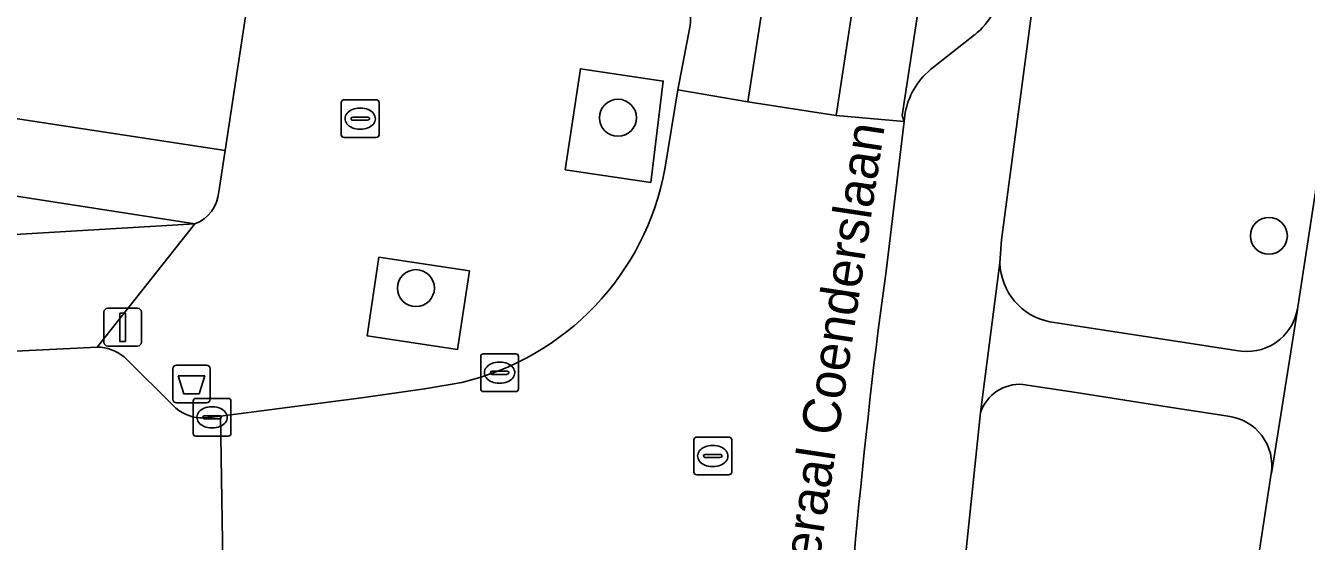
# Model space of a CAD drawing. Extents: x 161084 to 161928, y 385354 to 386522.
# Drawn here: x 161622.73 to 161656.61, y 385454.78 to 385468.42 of the extents above; entities that cross this region are included whole.
import ezdxf

# ---------------------------------------------------------------- set-up
doc = ezdxf.new("R2010")
doc.units = 0
for name, color, linetype in [('IMGEO_Afvalbak', 7, 'Continuous'), ('IMGEO_Boom', 7, 'Continuous'), ('IMGEO_Brandkraan', 7, 'Continuous'), ('IMGEO_Fietspad_gesloten', 7, 'Continuous'), ('IMGEO_Groenvoorziening', 7, 'Continuous'), ('IMGEO_Kolk', 7, 'Continuous'), ('IMGEO_Lichtmast', 7, 'Continuous'), ('IMGEO_Openbare_ruimte_label', 7, 'Continuous'), ('IMGEO_Pand', 7, 'Continuous'), ('IMGEO_Parkeervlak_open', 7, 'Continuous'), ('IMGEO_Rijbaan_lokaal_gesloten', 7, 'Continuous'), ('IMGEO_Rijbaan_lokaal_open', 7, 'Continuous'), ('IMGEO_Rioolput', 7, 'Continuous'), ('IMGEO_Voetpad_open', 7, 'Continuous')]:
    doc.layers.add(name, color=color, linetype=linetype)

msp = doc.modelspace()

# ---------------------------------------------------------------- linework, layer by layer
at = {"layer": 'IMGEO_Afvalbak'}
for p, q in [((161626.622, 385458.538), (161626.622, 385459.338)), ((161626.622, 385459.338), (161626.622, 385458.538)), ((161626.722, 385459.438), (161627.512, 385459.438)), ((161627.512, 385459.438), (161626.722, 385459.438)), ((161627.612, 385459.338), (161627.612, 385458.538)), ((161627.612, 385458.538), (161627.612, 385459.338)), ((161627.512, 385458.438), (161626.722, 385458.438)), ((161626.722, 385458.438), (161627.512, 385458.438))]:
    msp.add_line(p, q, dxfattribs=at)
msp.add_lwpolyline([(161626.765, 385459.152), (161627.469, 385459.152), (161627.32, 385458.682), (161626.914, 385458.682), (161626.765, 385459.152)], dxfattribs=at)
for centre, start, end in [((161626.722, 385459.338), 90, 180), ((161626.722, 385459.338), 90, 180), ((161627.512, 385459.338), 0, 90), ((161627.512, 385459.338), 360, 90), ((161626.722, 385458.538), 180, 270), ((161626.722, 385458.538), 180, 270), ((161627.512, 385458.538), 270, 0), ((161627.512, 385458.538), 270, 0)]:
    msp.add_arc(centre, 0.1, start, end, dxfattribs=at)
at = {"layer": 'IMGEO_Boom'}
for centre in [(161638.401, 385465.983), (161655.623, 385462.859), (161633.056, 385461.476)]:
    msp.add_circle(centre, 0.489, dxfattribs=at)
at = {"layer": 'IMGEO_Brandkraan'}
for p, q in [((161631.08, 385465.533), (161631.08, 385466.385)), ((161631.155, 385466.459), (161632.007, 385466.459)), ((161632.081, 385466.385), (161632.081, 385465.533)), ((161631.339, 385465.953), (161631.339, 385465.965)), ((161631.777, 385465.916), (161631.379, 385465.916)), ((161631.382, 385466.002), (161631.78, 385466.002)), ((161631.568, 385466.239), (161631.593, 385466.239)), ((161631.823, 385465.965), (161631.823, 385465.953)), ((161631.591, 385465.679), (161631.566, 385465.679)), ((161632.007, 385465.459), (161631.155, 385465.459))]:
    msp.add_line(p, q, dxfattribs=at)
for points in [[(161631.08, 385465.533), (161631.08, 385466.385)], [(161631.155, 385466.459), (161632.007, 385466.459)], [(161632.081, 385466.385), (161632.081, 385465.533)], [(161632.007, 385465.459), (161631.155, 385465.459)]]:
    msp.add_lwpolyline(points, dxfattribs=at)
for centre, radius, start, end in [((161631.157, 385466.383), 0.0765, 91.552, 178.448), ((161631.157, 385466.383), 0.0765, 91.552, 178.448), ((161632.005, 385466.383), 0.0765, 1.552, 88.448), ((161632.005, 385466.383), 0.0765, 1.552, 88.448), ((161631.379, 385465.962), 0.0403, 85.8775, 175.7526), ((161631.376, 385465.952), 0.0366, 178.938, 274.7102), ((161631.78, 385465.959), 0.043, 264.8664, 352.4533), ((161631.784, 385465.964), 0.0386, 1.7309, 96.639), ((161631.157, 385465.535), 0.0765, 181.552, 268.448), ((161631.157, 385465.535), 0.0765, 181.552, 268.448), ((161632.005, 385465.535), 0.0765, 271.552, 358.448), ((161632.005, 385465.535), 0.0765, 271.552, 358.448)]:
    msp.add_arc(centre, radius, start, end, dxfattribs=at)
for centre, major_axis, ratio, start_param, end_param in [((161631.567, 385465.959), (-0.387, 0.002), 0.722429, 4.712389, 7.853982), ((161631.592, 385465.959), (-0.39, 0.002), 0.717154, 1.570796, 4.712389)]:
    msp.add_ellipse(centre, major_axis=major_axis, ratio=ratio, start_param=start_param, end_param=end_param, dxfattribs=at)
at = {"layer": 'IMGEO_Fietspad_gesloten'}
for points in [[(161657.676, 385557.376), (161657.035, 385551.607), (161656.101, 385544.122), (161653.229, 385525.292), (161650.81, 385509.078), (161648.418, 385493.406), (161645.687, 385475.984), (161644.173, 385466.039), (161645.972, 385465.882), (161645.921, 385466.044), (161654.912, 385525.117), (161655.077, 385525.205), (161655.27, 385526.392)], [(161640.307, 385468.42), (161639.981, 385466.717), (161641.834, 385466.406), (161644.23, 385481.84), (161647.175, 385501.347), (161649.95, 385519.187)]]:
    msp.add_lwpolyline(points, dxfattribs=at)
msp.add_arc((161639.335, 385468.589), 0.987, 350.1456, 38.031, dxfattribs=at)
at = {"layer": 'IMGEO_Groenvoorziening'}
for points in [[(161656.38, 385460.922), (161658.19, 385472.711), (161661.817, 385496.26), (161663.625, 385508.283), (161667.803, 385536.052), (161668.116, 385538.133)], [(161661.208, 385537.956), (161659.14, 385524.383), (161657.879, 385524.571), (161655.178, 385507.25), (161651.761, 385484.769), (161649.596, 385470.673), (161648.548, 385462.752), (161648.507, 385462.144)], [(161649.829, 385460.581), (161650.74, 385460.441), (161653.046, 385460.089), (161654.755, 385459.827)], [(161654.544, 385458.088), (161652.934, 385458.337), (161650.52, 385458.711), (161649.115, 385458.928)], [(161647.993, 385458.185), (161647.537, 385453.796), (161647.198, 385449.946), (161647.015, 385446.776), (161646.866, 385440.852)], [(161653.085, 385439.584), (161655.028, 385452.288), (161655.683, 385456.575)]]:
    msp.add_lwpolyline(points, dxfattribs=at)
for points in [[(161637.008, 385464.609), (161639.269, 385464.266), (161639.601, 385466.954), (161637.407, 385467.281)], [(161634.472, 385461.937), (161632.074, 385462.292), (161631.765, 385460.216), (161634.155, 385459.85)]]:
    msp.add_lwpolyline(points, close=True, dxfattribs=at)
for centre, radius, start, end in [((161650.153, 385462.196), 1.647, 181.7969, 258.6528), ((161655.037, 385461.162), 1.364, 258.0731, 349.8747), ((161649.033, 385457.833), 1.098, 85.7166, 161.3093), ((161654.388, 385456.785), 1.312, 350.7925, 83.1531)]:
    msp.add_arc(centre, radius, start, end, dxfattribs=at)
at = {"layer": 'IMGEO_Kolk'}
for p, q in [((161634.769, 385458.812), (161634.769, 385459.664)), ((161634.844, 385459.738), (161635.696, 385459.738)), ((161635.257, 385459.518), (161635.282, 385459.518)), ((161635.77, 385459.664), (161635.77, 385458.812)), ((161635.028, 385459.232), (161635.028, 385459.244)), ((161635.466, 385459.195), (161635.068, 385459.195)), ((161635.071, 385459.281), (161635.469, 385459.281)), ((161635.512, 385459.244), (161635.512, 385459.232)), ((161635.28, 385458.958), (161635.255, 385458.958)), ((161627.16, 385457.632), (161627.16, 385458.484)), ((161627.235, 385458.558), (161628.087, 385458.558)), ((161628.161, 385458.484), (161628.161, 385457.632)), ((161635.696, 385458.738), (161634.844, 385458.738)), ((161627.648, 385458.338), (161627.673, 385458.338)), ((161627.419, 385458.052), (161627.419, 385458.064)), ((161627.857, 385458.015), (161627.459, 385458.015)), ((161627.462, 385458.101), (161627.86, 385458.101)), ((161627.671, 385457.778), (161627.646, 385457.778)), ((161627.903, 385458.064), (161627.903, 385458.052)), ((161628.087, 385457.558), (161627.235, 385457.558))]:
    msp.add_line(p, q, dxfattribs=at)
for points in [[(161634.769, 385458.812), (161634.769, 385459.664)], [(161634.844, 385459.738), (161635.696, 385459.738)], [(161635.77, 385459.664), (161635.77, 385458.812)], [(161627.16, 385457.632), (161627.16, 385458.484)], [(161627.235, 385458.558), (161628.087, 385458.558)], [(161628.161, 385458.484), (161628.161, 385457.632)], [(161635.696, 385458.738), (161634.844, 385458.738)], [(161628.087, 385457.558), (161627.235, 385457.558)]]:
    msp.add_lwpolyline(points, dxfattribs=at)
for centre, radius, start, end in [((161634.846, 385459.662), 0.0765, 91.552, 178.448), ((161634.846, 385459.662), 0.0765, 91.552, 178.448), ((161635.694, 385459.662), 0.0765, 1.552, 88.448), ((161635.694, 385459.662), 0.0765, 1.552, 88.448), ((161635.068, 385459.241), 0.0403, 85.8775, 175.7526), ((161635.065, 385459.231), 0.0366, 178.938, 274.7102), ((161635.469, 385459.238), 0.043, 264.8664, 352.4533), ((161635.473, 385459.243), 0.0386, 1.7309, 96.639), ((161634.846, 385458.814), 0.0765, 181.552, 268.448), ((161634.846, 385458.814), 0.0765, 181.552, 268.448), ((161635.694, 385458.814), 0.0765, 271.552, 358.448), ((161635.694, 385458.814), 0.0765, 271.552, 358.448), ((161627.237, 385458.482), 0.0765, 91.552, 178.448), ((161627.237, 385458.482), 0.0765, 91.552, 178.448), ((161628.085, 385458.482), 0.0765, 1.552, 88.448), ((161628.085, 385458.482), 0.0765, 1.552, 88.448), ((161627.459, 385458.061), 0.0403, 85.8775, 175.7526), ((161627.456, 385458.051), 0.0366, 178.938, 274.7102), ((161627.86, 385458.058), 0.043, 264.8664, 352.4533), ((161627.864, 385458.063), 0.0386, 1.7309, 96.639), ((161627.237, 385457.634), 0.0765, 181.552, 268.448), ((161627.237, 385457.634), 0.0765, 181.552, 268.448), ((161628.085, 385457.634), 0.0765, 271.552, 358.448), ((161628.085, 385457.634), 0.0765, 271.552, 358.448)]:
    msp.add_arc(centre, radius, start, end, dxfattribs=at)
for centre, major_axis, ratio, start_param, end_param in [((161635.256, 385459.238), (-0.387, 0.002), 0.722429, 4.712389, 7.853982), ((161635.281, 385459.238), (-0.39, 0.002), 0.717154, 1.570796, 4.712389), ((161627.647, 385458.058), (-0.387, 0.002), 0.722429, 4.712389, 7.853982), ((161627.672, 385458.058), (-0.39, 0.002), 0.717154, 1.570796, 4.712389)]:
    msp.add_ellipse(centre, major_axis=major_axis, ratio=ratio, start_param=start_param, end_param=end_param, dxfattribs=at)
at = {"layer": 'IMGEO_Lichtmast'}
for p, q in [((161624.8, 385460.042), (161624.8, 385460.842)), ((161624.8, 385460.842), (161624.8, 385460.042)), ((161624.9, 385460.942), (161625.69, 385460.942)), ((161625.69, 385460.942), (161624.9, 385460.942)), ((161625.79, 385460.842), (161625.79, 385460.042)), ((161625.79, 385460.042), (161625.79, 385460.842)), ((161625.69, 385459.942), (161624.9, 385459.942)), ((161624.9, 385459.942), (161625.69, 385459.942))]:
    msp.add_line(p, q, dxfattribs=at)
msp.add_lwpolyline([(161625.22, 385460.817), (161625.37, 385460.817), (161625.37, 385460.067), (161625.22, 385460.067), (161625.22, 385460.817)], dxfattribs=at)
for centre, start, end in [((161624.9, 385460.842), 90, 180), ((161624.9, 385460.842), 90, 180), ((161625.69, 385460.842), 0, 90), ((161625.69, 385460.842), 360, 90), ((161624.9, 385460.042), 180, 270), ((161624.9, 385460.042), 180, 270), ((161625.69, 385460.042), 270, 0), ((161625.69, 385460.042), 270, 0)]:
    msp.add_arc(centre, 0.1, start, end, dxfattribs=at)
at = {"layer": 'IMGEO_Pand'}
msp.add_lwpolyline([(161605.265, 385465.382), (161614.61, 385465.848), (161618.058, 385465.325), (161617.923, 385464.439), (161616.668, 385464.63), (161616.532, 385463.731), (161621.059, 385462.994), (161621.227, 385464.1), (161621.53, 385466.101), (161628.006, 385465.119), (161633.299, 385500), (161636.907, 385522.697), (161623.839, 385524.734), (161622.681, 385548.29), (161620.53, 385548.19), (161616.769, 385548.015), (161601.041, 385547.282), (161602.865, 385509.999), (161613.597, 385508.326), (161612.319, 385500), (161608.42, 385474.596), (161604.686, 385475.163), (161605.075, 385468.597)], close=True, dxfattribs=at)
at = {"layer": 'IMGEO_Parkeervlak_open'}
for points in [[(161655.077, 385525.205), (161654.912, 385525.117), (161645.921, 385466.044), (161645.972, 385465.882)], [(161646.466, 385467.062), (161646.666, 385467.256), (161647.832, 385468.172)]]:
    msp.add_lwpolyline(points, dxfattribs=at)
for centre, radius, start, end in [((161646.658, 385469.653), 1.89, 308.3894, 355.7454), ((161647.93, 385465.756), 1.962, 138.2595, 176.3078)]:
    msp.add_arc(centre, radius, start, end, dxfattribs=at)
at = {"layer": 'IMGEO_Rijbaan_lokaal_gesloten'}
msp.add_lwpolyline([(161654.621, 385550.774), (161652.131, 385533.824), (161649.95, 385519.187), (161647.175, 385501.347), (161644.23, 385481.84), (161641.834, 385466.406), (161644.173, 385466.039), (161645.687, 385475.984), (161648.418, 385493.406), (161650.81, 385509.078)], dxfattribs=at)
at = {"layer": 'IMGEO_Rijbaan_lokaal_open'}
for points in [[(161645.284, 385460.364), (161645.495, 385461.921), (161645.972, 385465.882), (161644.173, 385466.039), (161641.834, 385466.406), (161639.981, 385466.717), (161639.642, 385464.626)], [(161624.618, 385459.918), (161621.197, 385459.746), (161604.552, 385459.269), (161597.818, 385458.919), (161596.64, 385458.858), (161583.443, 385458.171), (161561.024, 385457.005), (161560.918, 385457), (161561.322, 385449.16), (161568.656, 385449.513), (161574.004, 385449.781)], [(161626.703, 385458.303), (161625.337, 385459.654)], [(161634.268, 385458.983), (161633.285, 385458.808), (161631.611, 385458.572), (161627.885, 385458.087), (161627.96, 385453.134), (161629.113, 385452.976), (161631.927, 385452.619)], [(161627.885, 385458.087), (161627.661, 385458.058), (161627.438, 385458.042)], [(161627.96, 385453.134), (161627.885, 385458.087)]]:
    msp.add_lwpolyline(points, dxfattribs=at)
for centre, radius, start, end in [((161632.635, 385465.918), 7.125, 283.2484, 349.549), ((161833.966, 385437.297), 190.087, 173.02986, 177.50061), ((161624.6, 385458.757), 1.161, 50.575, 89.1009), ((161627.397, 385459.091), 1.049, 228.6354, 272.2644)]:
    msp.add_arc(centre, radius, start, end, dxfattribs=at)
at = {"layer": 'IMGEO_Rioolput'}
for p, q in [((161640.409, 385456.609), (161640.409, 385457.461)), ((161640.484, 385457.535), (161641.336, 385457.535)), ((161641.41, 385457.461), (161641.41, 385456.609)), ((161640.897, 385457.315), (161640.922, 385457.315)), ((161640.668, 385457.029), (161640.668, 385457.041)), ((161641.106, 385456.992), (161640.708, 385456.992)), ((161640.711, 385457.078), (161641.109, 385457.078)), ((161641.152, 385457.041), (161641.152, 385457.029)), ((161641.336, 385456.535), (161640.484, 385456.535)), ((161640.92, 385456.755), (161640.895, 385456.755))]:
    msp.add_line(p, q, dxfattribs=at)
for points in [[(161640.409, 385456.609), (161640.409, 385457.461)], [(161640.484, 385457.535), (161641.336, 385457.535)], [(161641.41, 385457.461), (161641.41, 385456.609)], [(161641.336, 385456.535), (161640.484, 385456.535)]]:
    msp.add_lwpolyline(points, dxfattribs=at)
for centre, radius, start, end in [((161640.486, 385457.459), 0.0765, 91.552, 178.448), ((161640.486, 385457.459), 0.0765, 91.552, 178.448), ((161641.334, 385457.459), 0.0765, 1.552, 88.448), ((161641.334, 385457.459), 0.0765, 1.552, 88.448), ((161640.708, 385457.038), 0.0403, 85.8775, 175.7526), ((161640.705, 385457.028), 0.0366, 178.938, 274.7102), ((161641.109, 385457.035), 0.043, 264.8664, 352.4533), ((161641.113, 385457.04), 0.0386, 1.7309, 96.639), ((161640.486, 385456.611), 0.0765, 181.552, 268.448), ((161640.486, 385456.611), 0.0765, 181.552, 268.448), ((161641.334, 385456.611), 0.0765, 271.552, 358.448), ((161641.334, 385456.611), 0.0765, 271.552, 358.448)]:
    msp.add_arc(centre, radius, start, end, dxfattribs=at)
for centre, major_axis, ratio, start_param, end_param in [((161640.896, 385457.035), (-0.387, 0.002), 0.722429, 4.712389, 7.853982), ((161640.921, 385457.035), (-0.39, 0.002), 0.717154, 1.570796, 4.712389)]:
    msp.add_ellipse(centre, major_axis=major_axis, ratio=ratio, start_param=start_param, end_param=end_param, dxfattribs=at)
at = {"layer": 'IMGEO_Voetpad_open'}
for points in [[(161682.306, 385629.936), (161677.325, 385598.393), (161675.404, 385586.149), (161674.661, 385580.545), (161674.034, 385576.484), (161672.366, 385565.674), (161668.928, 385543.394), (161668.239, 385538.924), (161668.116, 385538.133), (161667.803, 385536.052), (161663.625, 385508.283), (161661.817, 385496.26), (161658.19, 385472.711), (161656.38, 385460.922), (161656.38, 385460.904), (161655.699, 385456.628), (161655.683, 385456.575), (161655.028, 385452.288)], [(161640.593, 385509.875), (161642.132, 385519.767), (161636.907, 385522.697), (161633.299, 385500), (161628.006, 385465.119), (161627.84, 385464.022)], [(161646.866, 385440.852), (161647.015, 385446.776), (161647.198, 385449.946), (161647.537, 385453.796), (161647.993, 385458.185), (161648.507, 385462.144), (161648.548, 385462.752), (161649.596, 385470.673), (161651.761, 385484.769), (161655.178, 385507.25)], [(161639.642, 385464.626), (161639.981, 385466.717), (161640.307, 385468.42)], [(161647.832, 385468.172), (161646.666, 385467.256), (161646.466, 385467.062)], [(161627.84, 385464.022), (161628.006, 385465.119), (161621.53, 385466.101), (161621.227, 385464.1), (161627.202, 385463.173)], [(161645.972, 385465.882), (161645.495, 385461.921), (161645.284, 385460.364)], [(161627.202, 385463.173), (161624.618, 385459.918)], [(161648.507, 385462.144), (161647.993, 385458.185)], [(161655.683, 385456.575), (161655.699, 385456.628), (161656.38, 385460.904), (161656.38, 385460.922)], [(161654.755, 385459.827), (161653.046, 385460.089), (161650.74, 385460.441), (161649.829, 385460.581)], [(161625.337, 385459.654), (161626.703, 385458.303)], [(161627.438, 385458.042), (161627.661, 385458.058), (161627.885, 385458.087), (161631.611, 385458.572), (161633.285, 385458.808), (161634.268, 385458.983)], [(161649.115, 385458.928), (161650.52, 385458.711), (161652.934, 385458.337), (161654.544, 385458.088)]]:
    msp.add_lwpolyline(points, dxfattribs=at)
for points in [[(161639.601, 385466.954), (161639.269, 385464.266), (161637.008, 385464.609), (161637.407, 385467.281)], [(161621.227, 385464.1), (161621.059, 385462.994), (161616.532, 385463.731), (161616.668, 385464.63), (161617.923, 385464.439), (161618.058, 385465.325), (161614.61, 385465.848), (161605.265, 385465.382), (161605.413, 385462.887), (161605.554, 385462.466), (161605.854, 385462.14), (161606.553, 385461.95), (161627.202, 385463.173)], [(161627.202, 385463.173), (161606.553, 385461.95), (161605.854, 385462.14), (161603.364, 385462.015), (161603.488, 385459.684), (161604.527, 385459.739), (161604.552, 385459.269), (161621.197, 385459.746), (161624.618, 385459.918)], [(161634.472, 385461.937), (161634.155, 385459.85), (161631.765, 385460.216), (161632.074, 385462.292)]]:
    msp.add_lwpolyline(points, close=True, dxfattribs=at)
for centre, radius, start, end in [((161646.658, 385469.653), 1.89, 308.3894, 355.7454), ((161639.335, 385468.589), 0.987, 350.1456, 38.031), ((161647.93, 385465.756), 1.962, 138.2595, 176.3078), ((161632.635, 385465.918), 7.125, 283.2484, 349.549), ((161626.843, 385464.107), 1.001, 291.0287, 355.1236), ((161626.843, 385464.107), 1.001, 291.0287, 355.1236), ((161650.153, 385462.196), 1.647, 181.7969, 258.6528), ((161655.037, 385461.162), 1.364, 258.0731, 349.8747), ((161833.966, 385437.297), 190.087, 173.02986, 177.50061), ((161624.6, 385458.757), 1.161, 50.575, 89.1009), ((161649.033, 385457.833), 1.098, 85.7166, 161.3093), ((161627.397, 385459.091), 1.049, 228.6354, 272.2644), ((161654.388, 385456.785), 1.312, 350.7925, 83.1531)]:
    msp.add_arc(centre, radius, start, end, dxfattribs=at)

# ---------------------------------------------------------------- texts
at = {"layer": 'IMGEO_Openbare_ruimte_label'}
msp.add_text('Generaal Coenderslaan', height=1, rotation=81.4324, dxfattribs=at).set_placement((161643.347, 385451.73))

doc.saveas('drawing.dxf')
